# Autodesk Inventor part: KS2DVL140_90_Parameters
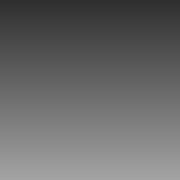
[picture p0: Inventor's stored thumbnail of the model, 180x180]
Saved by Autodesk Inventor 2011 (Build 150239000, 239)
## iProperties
Created: 2010-11
Document SubType Name: Modeling
Designer: TB
Density: 1 g/cm^3
Slaglengde: 100,000 mm
Vinkel_Minusport: 0.00 deg
Forlengelse_rør: 0.000 mm
Minusport2: 180.00 deg
Author: TB
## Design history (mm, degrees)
other parameters: "Slaglengde" = 100 [user parameter], "Forlengelse_rør" = 0 [user parameter], "Vinkel_Minusport" = 0 deg [user parameter], "Minusport2" = 180 deg [user parameter]
